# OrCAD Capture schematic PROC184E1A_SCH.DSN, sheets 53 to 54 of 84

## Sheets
53 58. USB TYPE C 3.1: size C; title: USB 3.1 TYPE C INTERFACE; note: PROC184_SCH
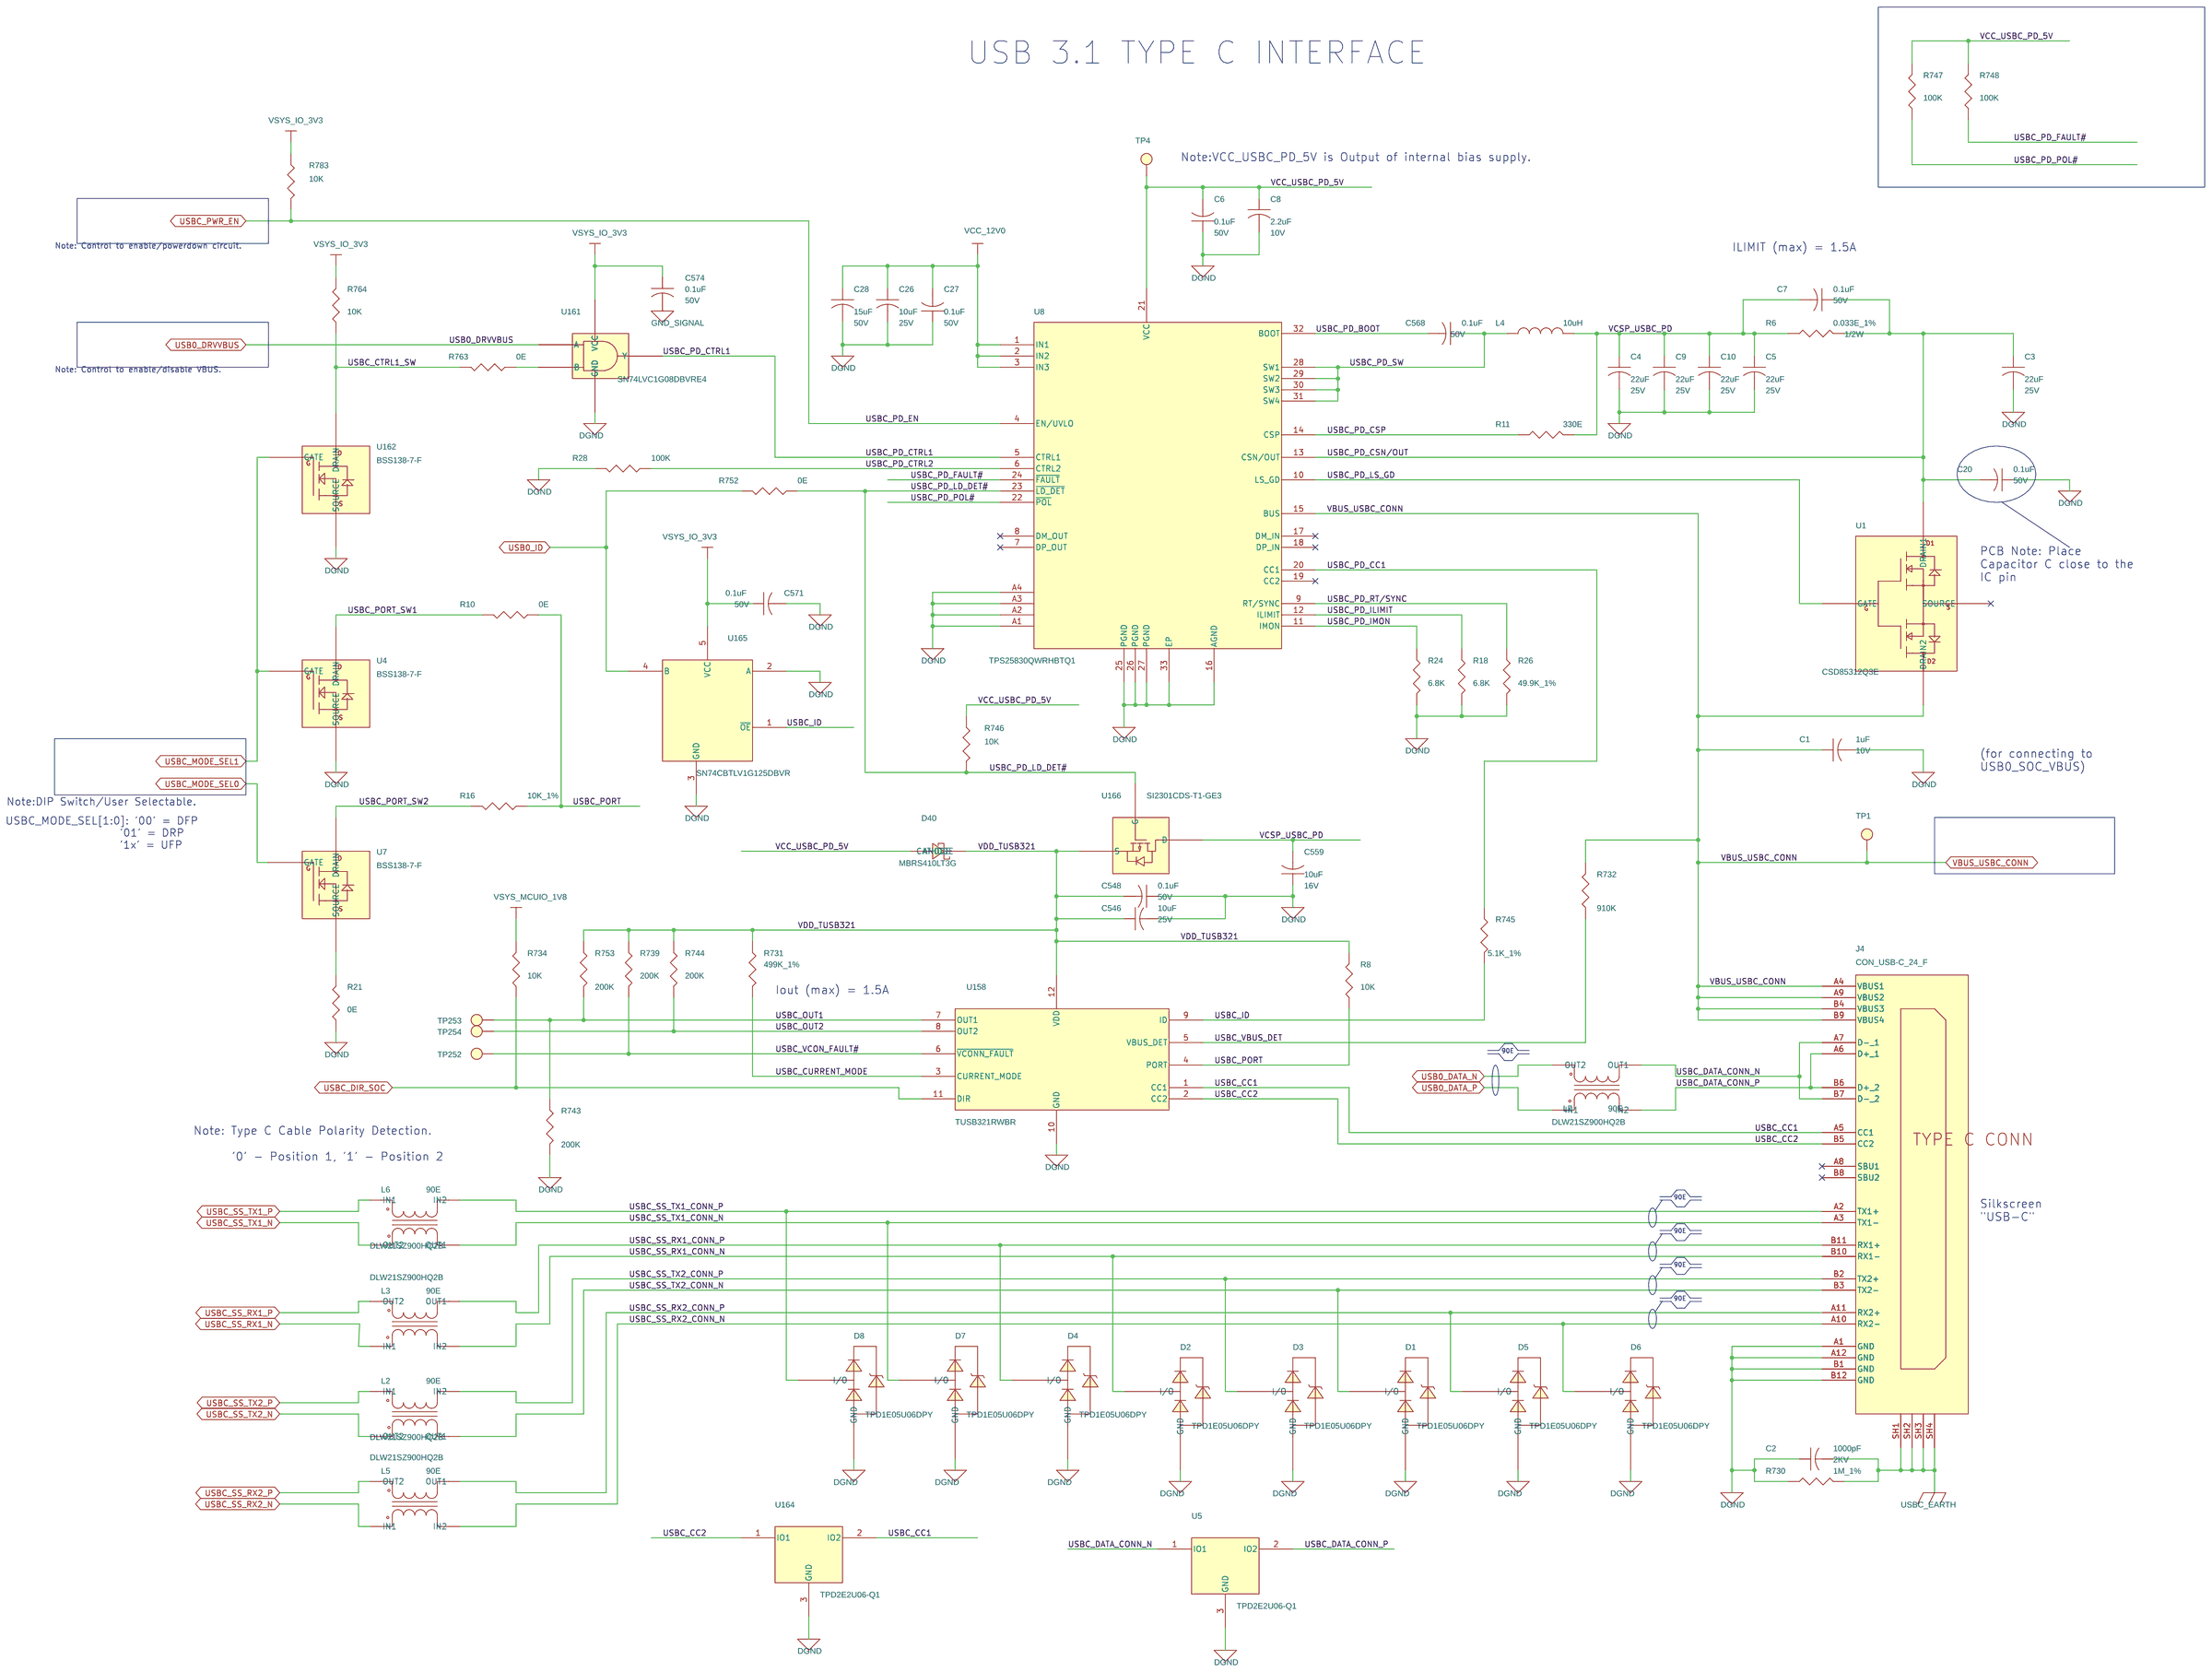
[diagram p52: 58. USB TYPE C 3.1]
54 32. SVS MONITOR: size C; title: SVS MONITOR; note: PROC184_SCH
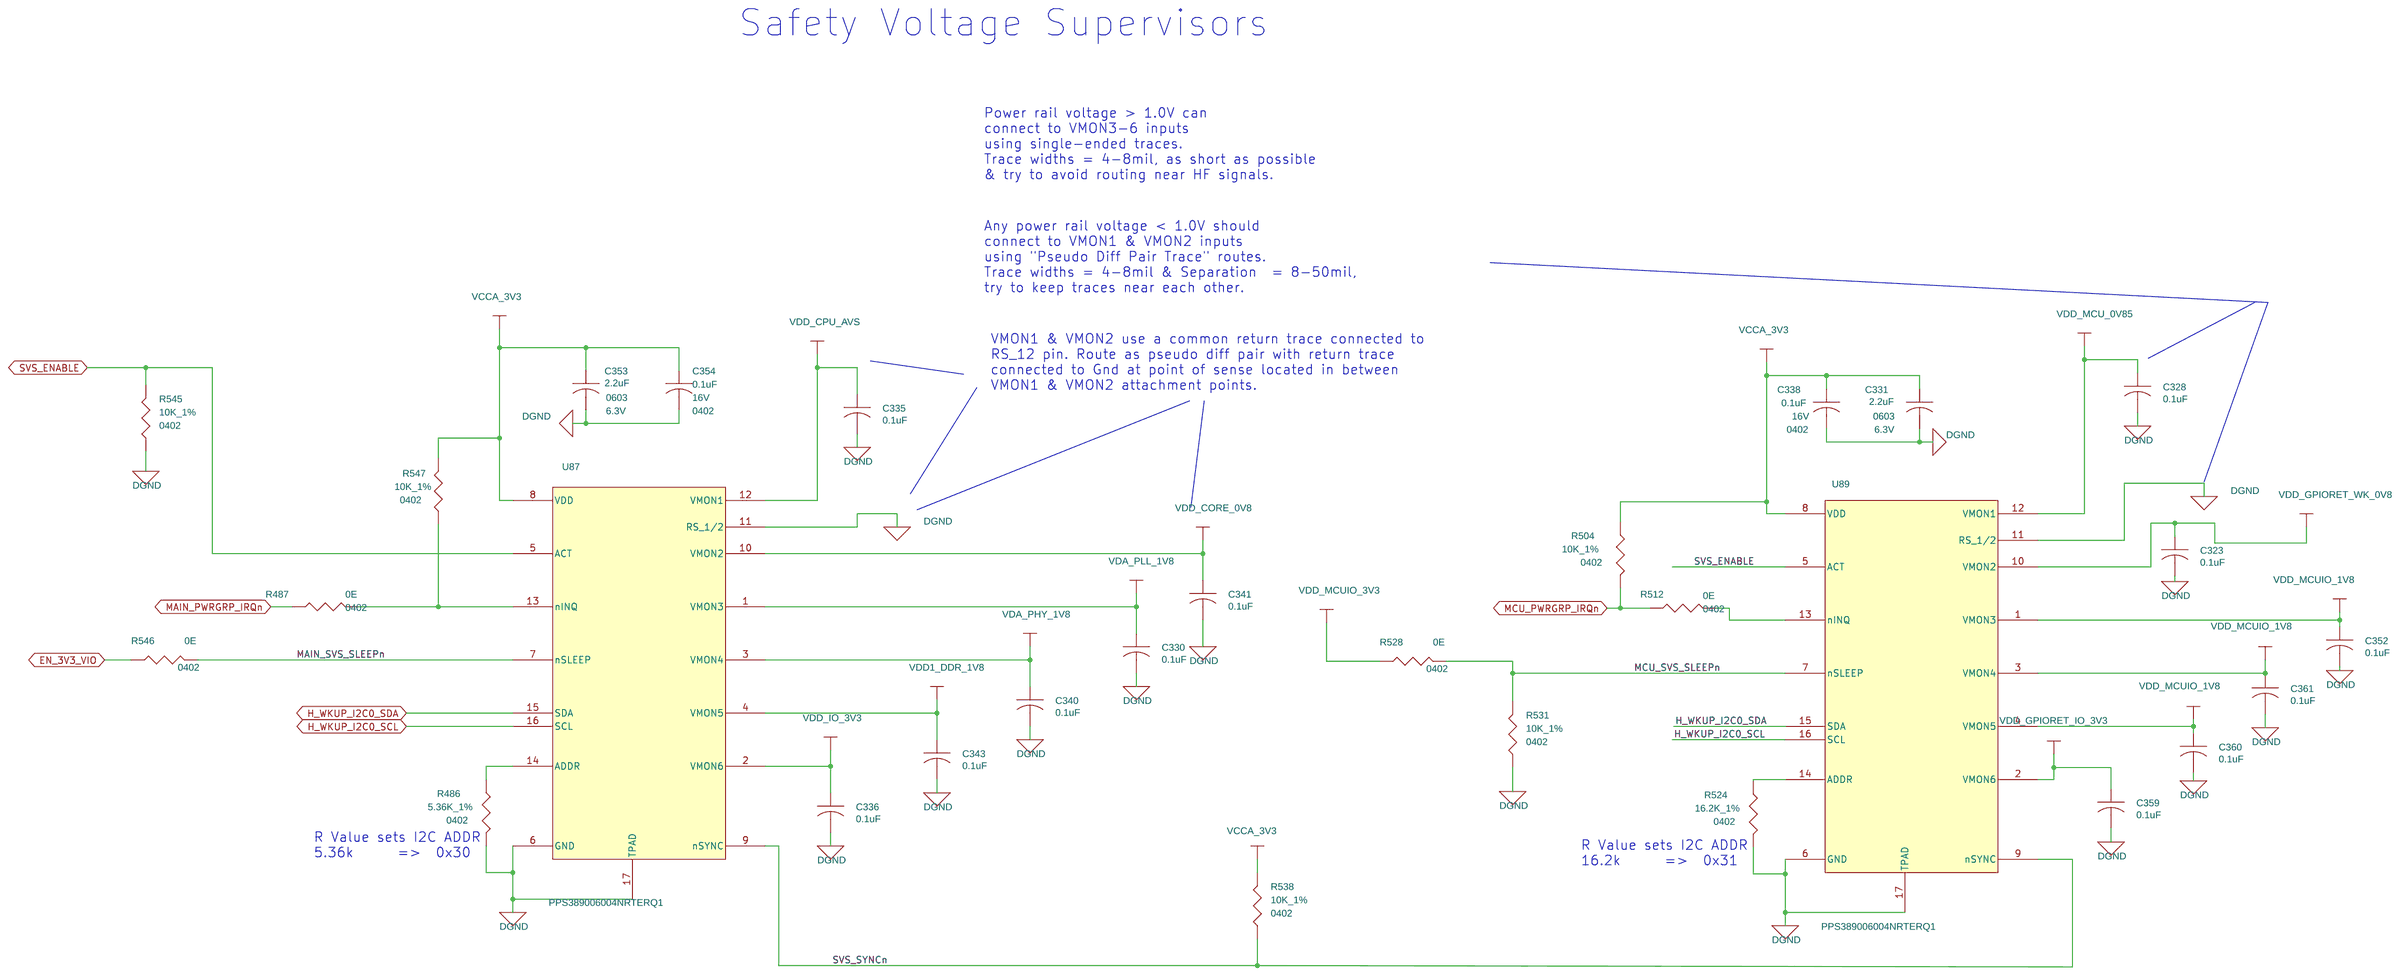
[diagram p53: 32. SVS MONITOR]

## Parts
sheet 32. SVS MONITOR
C323  0.1uF  [CAP0201_0-5]
C328  0.1uF  [CAP0201_0-5]
C330  0.1uF  [CAP0201_0-5]
C331  2.2uF  [CAP0603_1]
C335  0.1uF  [CAP0201_0-5]
C336  0.1uF  [CAP0201_0-5]
C338  0.1uF  [CAP0402_0-75]
C340  0.1uF  [CAP0201_0-5]
C341  0.1uF  [CAP0201_0-5]
C343  0.1uF  [CAP0201_0-5]
C352  0.1uF  [CAP0201_0-5]
C353  2.2uF  [CAP0603_1]
C354  0.1uF  [CAP0402_0-75]
C359  0.1uF  [CAP0201_0-5]
C360  0.1uF  [CAP0201_0-5]
C361  0.1uF  [CAP0201_0-5]
R486  5.36K_1%  [RES0402_0-5]
R487  0E  [RES0402_0-5]
R504  10K_1%  [RES0402_0-5]
R512  0E  [RES0402_0-5]
R524  16.2K_1%  [RES0402_0-5]
R528  0E  [RES0402_0-5]
R531  10K_1%  [RES0402_0-5]
R538  10K_1%  [RES0402_0-5]
R545  10K_1%  [RES0402_0-5]
R546  0E  [RES0402_0-5]
R547  10K_1%  [RES0402_0-5]
U87  PPS389006004NRTERQ1  [QFN16_19-68_120X120_0-8_EP1-8]
U89  PPS389006004NRTERQ1  [QFN16_19-68_120X120_0-8_EP1-8]
sheet 58. USB TYPE C 3.1
C1  1uF  [CAP0402_0-75]
C2  1000pF  [CAP1206_1-75]
C3  22uF  [CAP0805_1-5]
C4  22uF  [CAP0805_1-5]
C5  22uF  [CAP0805_1-5]
C6  0.1uF  [CAP0402_0-75]
C7  0.1uF  [CAP0402_0-75]
C8  2.2uF  [CAP0402_0-75]
C9  22uF  [CAP0805_1-5]
C10  22uF  [CAP0805_1-5]
C20  0.1uF  [CAP0402_0-75]
C26  10uF  [CAP0603_1-25]
C27  0.1uF  [CAP0402_0-75]
C28  15uF  [CAP2220_2-75]
C546  10uF  [CAP0603_1-25]
C548  0.1uF  [CAP0402_0-75]
C559  10uF  [CAP0805_1-5]
C568  0.1uF  [CAP0402_0-75]
C571  0.1uF  [CAP0402_0-75]
C574  0.1uF  [CAP0402_0-75]
D1  TPD1E05U06DPY  [DIO_DFN0402_0-5]
D2  TPD1E05U06DPY  [DIO_DFN0402_0-5]
D3  TPD1E05U06DPY  [DIO_DFN0402_0-5]
D4  TPD1E05U06DPY  [DIO_DFN0402_0-5]
D5  TPD1E05U06DPY  [DIO_DFN0402_0-5]
D6  TPD1E05U06DPY  [DIO_DFN0402_0-5]
D7  TPD1E05U06DPY  [DIO_DFN0402_0-5]
D8  TPD1E05U06DPY  [DIO_DFN0402_0-5]
D40  MBRS410LT3G  [DIO_SMC]
J4  CON_USB-C_24_F  [CON_USBC24_2012670_S_R_S_3-9]
L2  90E  [IND4_DLW21H_90X60_SMD_1-4]
L3  90E  [IND4_DLW21H_90X60_SMD_1-4]
L4  10uH  [IND_ASPI-0603LR_270X270_SMD_3]
L5  90E  [IND4_DLW21H_90X60_SMD_1-4]
L6  90E  [IND4_DLW21H_90X60_SMD_1-4]
L7  90E  [IND4_DLW21H_90X60_SMD_1-4]
R6  0.033E_1%  [RES1210_0-75]
R8  10K  [RES0402_0-5]
R10  0E  [RES0402_0-5]
R11  330E  [RES0402_0-5]
R16  10K_1%  [RES0402_0-5]
R18  6.8K  [RES0402_0-5]
R21  0E  [RES0402_0-5]
R24  6.8K  [RES0402_0-5]
R26  49.9K_1%  [RES0402_0-5]
R28  100K  [RES0402_0-5]
R730  1M_1%  [RES0805_0-75]
R731  499K_1%  [RES0402_0-5]
R732  910K  [RES0402_0-5]
R734  10K  [RES0402_0-5]
R739  200K  [RES0402_0-5]
R743  200K  [RES0402_0-5]
R744  200K  [RES0402_0-5]
R745  5.1K_1%  [RES0402_0-5]
R746  10K  [RES0402_0-5]
R747  100K  [RES0402_0-5]
R748  100K  [RES0402_0-5]
R752  0E  [RES0402_0-5]
R753  200K  [RES0402_0-5]
R763  0E  [RES0402_0-5]
R764  10K  [RES0402_0-5]
R783  10K  [RES0402_0-5]
TP1  THRU HOLE  [TP_40X65]
TP4  TP30_SMD  [TP30_SMD]
TP252  TP30_SMD  [TP30_SMD]
TP253  TP30_SMD  [TP30_SMD]
TP254  TP30_SMD  [TP30_SMD]
U1  CSD85312Q3E  [VSON8_CSD85312Q3E_130X130_1]
U4  BSS138-7-F  [SOT23-123_1-1]
U5  TPD2E2U06-Q1  [SC70-3_1-1]
U7  BSS138-7-F  [SOT23-123_1-1]
U8  TPS25830QWRHBTQ1  [VQFN32_TPS25830-Q1_200X200_1]
U158  TUSB321RWBR  [X2QFN12_TUSB322I_60X60_0-4]
U161  SN74LVC1G08DBVRE4  [SOT23-5]
U162  BSS138-7-F  [SOT23-123_1-1]
U164  TPD2E2U06-Q1  [SC70-3_1-1]
U165  SN74CBTLV1G125DBVR  [SOT23-5]
U166  SI2301CDS-T1-GE3  [SOT23-123]

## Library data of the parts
C323 C328 C330 C335 C336 C340 C341 C343 C352 C359-C361 = CAP: CAP CERAMIC 0.1uF 6.3V 10% X7S AUTO 0201; Chkd/date: MANIRAJA/011018; Crtd /date: MANIRAJA/011018; Custom_Duty: 15%; Customs_HS_Code: 85322990; Distributor_name: NA; Distributor_part_number: NA; Footprint Path: Y:\MIS_DATABASE\Library\ALTIUM_TOOL\PCB_FOOTPRINTS\Altium_Footprint_Lib.PcbLib; Height: 0.33MM; Library Path: Y:\MIS_DATABASE\Library\ALTIUM_TOOL\SCHEMATICS_PARTS\MS_DISCRETE_Library.schlib; Mfr_name: MURATA; Mfr_part_number: GCM033C70J104KE02D; Mistral Part No: 120018100001-R; Package: 0201; Part_type: CAPACITORS\CERAMIC; Project: TI_J7_SVB-DUT; RoHS: RoHS; Temperature: -55°C+125°C; Tolerance: 10%; Voltage: 6.3V; Wattage: NA; Weight: NA; Datasheet: Y:\MIS_DATABASE\DATASHEETS\CAPACITORS\MURATA-GCM-SER.PDF
C331 C353 = CAP: CAP CERAMIC 2.2uF 6.3V 10% X7R AUTO 0603; Automotive Alternate_mfr_name: TDK; Automotive Alternate_mfr_part_number: CGA3E1X7R0J225K080AC; Chkd/date: MANIRAJA/050419; Crtd /date: ALVY/050419; Custom_Duty: 15%; Customs_HS_Code: 85322990; Direct Alternate_mfr_name: TDK; Direct Alternate_mfr_part_number: CGA3E1X7R0J225K080AC; Distributor_name: DIGIKEY; Distributor_part_number: 490-5316-1-ND; Footprint Path: Y:\MIS_DATABASE\Library\ALTIUM_TOOL\PCB_FOOTPRINTS\Altium_Footprint_Lib.PcbLib; Height: 0.90MM; Library Path: Y:\MIS_DATABASE\Library\ALTIUM_TOOL\SCHEMATICS_PARTS\MS_DISCRETE_Library.schlib; Manufacturer: MURATA; Mfr_name: MURATA; Mfr_part_number: GCM188R70J225KE22D; Mistral Part No: 120019040009-R; Package: 0603; Part_type: CAPACITORS\CERAMIC; Project: J7ES_SOM_DUAL-LEO_PMIC; RoHS: RoHS; Temperature: -55°C+125°C; Tolerance: 10%; Voltage: 6.3V; Wattage: NA; Weight: 6.3mg; Datasheet: Y:\MIS_DATABASE\DATASHEETS\CAPACITORS\GCM188R70J225KE22.PDF
C338 C354 = CAP: CAP CERAMIC 0.1uF 16V 10% X7R AUTO 0402; Automotive Alternate_mfr_name: TDK; Automotive Alternate_mfr_part_number: CGA2B1X7R1C104K050BC; Chkd/date: NAVEED/021014; Crtd /date: VASANTHA/300514; Custom_Duty: 15%; Customs_HS_Code: 85322990; Direct Alternate_mfr_name: MURATA; Direct Alternate_mfr_part_number: GCM155R71C104JA55D; Distributor_name: DIGIKEY; Distributor_part_number: 490-4759-1-ND; Footprint Path: Y:\MIS_DATABASE\Library\ALTIUM_TOOL\PCB_FOOTPRINTS\Altium_Footprint_Lib.PcbLib; Height: 0.55MM; Library Path: Y:\MIS_DATABASE\Library\ALTIUM_TOOL\SCHEMATICS_PARTS\MS_DISCRETE_Library.schlib; Manufacturer: MURATA; Mfr_name: MURATA; Mfr_part_number: GCM155R71C104KA55D; Mistral Part No: 120016070006-R; Package: 0402; Part_type: CAPACITORS\CERAMIC; Project: DCMIST_FPGA_CARD; RoHS: RoHS; Temperature: -55°C+125°C; Tolerance: 10%; Voltage: 16V; Wattage: NA; Weight: 6mg; Datasheet: Y:\MIS_DATABASE\DATASHEETS\CAPACITORS\MURATA-GCM-SER.PDF
R486 = RESISTOR: RES 5.36K 1/16W 1% 0402; Chkd/date: MANIRAJA/120617; Crtd /date: BAVISH/220611; Custom_Duty: 15%; Customs_HS_Code: 85332119; Distributor_name: DIGIKEY; Distributor_part_number: 541-5.36KLCT-ND; Footprint Path: Y:\MIS_DATABASE\Library\ALTIUM_TOOL\PCB_FOOTPRINTS\Altium_Footprint_Lib.PcbLib; Height: 0.40MM; Library Path: Y:\MIS_DATABASE\Library\ALTIUM_TOOL\SCHEMATICS_PARTS\MS_DISCRETE_Library.schlib; Manufacturer: YAGEO AMERICA; Mfr_name: VISHAY; Mfr_part_number: CRCW04025K36FKED; Mistral Part No: 110011060044-R; Package: 0402; Part_type: RESISTORS\FIXED; Project: ITS-PWR_CARD; RoHS: RoHS; Temperature: -55°C+155°C; Tolerance: 1%; Voltage: NA; Wattage: 1/16W; Weight: 0.65mg; Datasheet: Y:\MIS_DATABASE\DATASHEETS\RESISTORS\CRCW0603.PDF
R10 R21 R487 R512 R528 R546 R763 = RESISTOR: RES 0E 1/10W JUMPER 0402; Chkd/date: VASANTHA/061216; Crtd /date: NAVEED/201014; Custom_Duty: 15%; Customs_HS_Code: 85332119; Distributor_name: DIGIKEY; Distributor_part_number: P0.0JCT-ND; Footprint Path: Y:\MIS_DATABASE\Library\ALTIUM_TOOL\PCB_FOOTPRINTS\Altium_Footprint_Lib.PcbLib; Height: 0.40MM; IBISSP_MODLES: VALUE REPEATING 2 TIME; Library Path: Y:\MIS_DATABASE\Library\ALTIUM_TOOL\SCHEMATICS_PARTS\MS_DISCRETE_Library.schlib; Manufacturer: PANASONIC-ECG; Mfr_name: PANASONIC-ECG; Mfr_part_number: ERJ-2GE0R00X; Mistral Part No: 110018030052-R; Package: 0402; Part_type: RESISTORS\FIXED; Project: AEGIS POM; RoHS: RoHS; Temperature: -55°C+155°C; Tolerance: NA; Voltage: NA; Wattage: 1/10W; Weight: 0.8mg; Datasheet: Y:\MIS_DATABASE\DATASHEETS\RESISTORS\PAN-ERJSER_NOV17.PDF
R16 R504 R531 R538 R545 R547 = RESISTOR: RES 10K 1/16W 1% 0402; Chkd/date: VASANTHA/201216; Crtd /date: GEETHA/290506; Custom_Duty: 15%; Customs_HS_Code: 85332119; Distributor_name: DIGIKEY; Distributor_part_number: 311-10.0KLRTR-ND; Footprint Path: Y:\MIS_DATABASE\Library\ALTIUM_TOOL\PCB_FOOTPRINTS\Altium_Footprint_Lib.PcbLib; Height: 0.40MM; Library Path: Y:\MIS_DATABASE\Library\ALTIUM_TOOL\SCHEMATICS_PARTS\MS_DISCRETE_Library.schlib; Manufacturer: YAGEO AMERICA; Mfr_name: YAGEO AMERICA; Mfr_part_number: RC0402FR-0710KL; Mistral Part No: 110015090015-R; Package: 0402; Part_type: RESISTORS\FIXED; Project: VOCERA; RoHS: RoHS; Temperature: -55°C+155°C; Tolerance: 1%; Voltage: NA; Wattage: 1/16W; Weight: 0.65mg; Datasheet: Y:\MIS_DATABASE\DATASHEETS\RESISTORS\RCXXXXL-SER_MAR18.PDF
R524 = RESISTOR: RES 16.2K 1/16W 1% AUTO 0402; Chkd/date: MANIRAJA/130617; Crtd /date: MAZHAR/270809; Custom_Duty: 15%; Customs_HS_Code: 85332119; Distributor_name: DIGIKEY; Distributor_part_number: RHM16.2KLCT-ND; Footprint Path: Y:\MIS_DATABASE\Library\ALTIUM_TOOL\PCB_FOOTPRINTS\Altium_Footprint_Lib.PcbLib; Height: 0.40MM; Library Path: Y:\MIS_DATABASE\Library\ALTIUM_TOOL\SCHEMATICS_PARTS\MS_DISCRETE_Library.schlib; Manufacturer: YAGEO AMERICA; Mfr_name: ROHM; Mfr_part_number: MCR01MZPF1622; Mistral Part No: 110009080027-R; Package: 0402; Part_type: RESISTORS\FIXED; Project: GEACOM_PHRAZER; RoHS: RoHS; Temperature: -55°C+155°C; Tolerance: 1%; Voltage: NA; Wattage: 1/16W; Weight: 0.57mg; Datasheet: Y:\MIS_DATABASE\DATASHEETS\RESISTORS\MCR10.PDF
U87 U89 = PPS38900603NRTERQ1_WQFN16: IC MULTI-CH OVERVOLTAGE AND UNDERVOLTAGE I2C PROGRAMMABLE VOLTAGE SUPERVISOR AND MONITOR WQFN16; Chkd/date: PRAVEEN/190722; Crtd /date: TAMILARASU/210722; Custom_Duty: 15%; Customs_HS_Code: 85423100; Distributor_name: NA; Distributor_part_number: NA; Footprint Path: Y:\MIS_DATABASE\Library\ALTIUM_TOOL\PCB_FOOTPRINTS\Altium_Footprint_Lib.PcbLib; Height: 0.80MM; Library Path: Y:\MIS_DATABASE\Library\ALTIUM_TOOL\SCHEMATICS_PARTS\MS_MISCPOWER_Library.schlib; Mfr_name: TEXAS INSTRUMENTS; Mistral Part No: 142022070022-R; Package: WQFN16; Part_type: ICS\POWER\MANAGEMENT; Project: TI_J7AHP_EVM_BRD; RoHS: NA; Temperature: -40°C+125°C; Tolerance: NA; Voltage: NA; Wattage: NA; Weight: NA; Datasheet: Y:\MIS_DATABASE\DATASHEETS\ICS\POWER\TPS389006-Q1.PDF
C1 = CAP: CAP CERAMIC 1uF 10V 10% X7S AUTO 0402; Automotive Alternate_mfr_name: TAIYO YUDEN; Automotive Alternate_mfr_part_number: EMK105BJ105KVHF; Chkd/date: MANIRAJA/100918; Crtd /date: ALVY/100918; Custom_Duty: 15%; Customs_HS_Code: 85322990; Direct Alternate_mfr_name: YAGEO AMERICA; Direct Alternate_mfr_part_number: CC0402KRX5R7BB105; Distributor_name: DIGIKEY; Distributor_part_number: 490-13409-1-ND; Footprint Path: Y:\MIS_DATABASE\Library\ALTIUM_TOOL\PCB_FOOTPRINTS\Altium_Footprint_Lib.PcbLib; Height: 0.70MM; Library Path: Y:\MIS_DATABASE\Library\ALTIUM_TOOL\SCHEMATICS_PARTS\MS_DISCRETE_Library.schlib; Manufacturer: TDK CORPORATION; Mfr_name: MURATA; Mfr_part_number: GCM155C71A105KE38D; Mistral Part No: 120018090021-R; Package: 0402; Part_type: CAPACITORS\CERAMIC; Project: SMART-M_SCRIPTALK_PB; RoHS: RoHS; Temperature: -55°C+125°C; Tolerance: 10%; Voltage: 10V; Wattage: NA; Weight: 6mg; Datasheet: Y:\MIS_DATABASE\DATASHEETS\CAPACITORS\MURATA-GCM-SER.PDF
C2 = CAP: CAP CERAMIC 1000pF 2KV 10% X7R 1206; Automotive Alternate_mfr_name: KEMET; Automotive Alternate_mfr_part_number: C1206X102KGRACAUTO; Chkd/date: SHREESHAIL/291106; Crtd /date: MAZHAR/281106; Custom_Duty: 15%; Customs_HS_Code: 85322990; Direct Alternate_mfr_name: KEMET; Direct Alternate_mfr_part_number: C1206C102KGRACTU; Distributor_name: DIGIKEY; Distributor_part_number: 478-2956-1-ND; Footprint Path: Y:\MIS_DATABASE\Library\ALTIUM_TOOL\PCB_FOOTPRINTS\Altium_Footprint_Lib.PcbLib; Height: 1.52MM; Library Path: Y:\MIS_DATABASE\Library\ALTIUM_TOOL\SCHEMATICS_PARTS\MS_DISCRETE_Library.schlib; Manufacturer: AVX CORPORATION; Mfr_name: AVX CORPORATION; Mfr_part_number: 1206GC102KAT1A; Mistral Part No: 120015080006-R; Package: 1206; Part_type: CAPACITORS\CERAMIC; Project: ADR1B; RoHS: RoHS; Temperature: -55°C+125°C; Tolerance: 10%; Voltage: 2KV; Wattage: NA; Weight: 16.2mg; Datasheet: Y:\MIS_DATABASE\DATASHEETS\CAPACITORS\AVX_HV-MLC.PDF
C3-C5 C9 C10 = CAP: CAP CERAMIC 22uF 25V 20% X5R 0805; Automotive Alternate_mfr_name: MURATA; Automotive Alternate_mfr_part_number: GRT21BR61E226ME13L; Chkd/date: USMAN/191213; Crtd /date: USMAN/191213; Custom_Duty: 15%; Customs_HS_Code: 85322990; Direct Alternate_mfr_name: MURATA; Direct Alternate_mfr_part_number: GRM21BR61E226ME44L; Distributor_name: DIGIKEY; Distributor_part_number: 1276-2908-1-ND; Footprint Path: Y:\MIS_DATABASE\Library\ALTIUM_TOOL\PCB_FOOTPRINTS\Altium_Footprint_Lib.PcbLib; Height: 1.40MM; Library Path: Y:\MIS_DATABASE\Library\ALTIUM_TOOL\SCHEMATICS_PARTS\MS_DISCRETE_Library.schlib; Manufacturer: SAMSUNG; Mfr_name: SAMSUNG; Mfr_part_number: CL21A226MAQNNNE; Mistral Part No: 120013120018-R; Package: 0805; Part_type: CAPACITORS\CERAMIC; Project: ITS2_RF; RoHS: RoHS; Temperature: -55°C+85°C; Tolerance: 20%; Voltage: 25V; Wattage: NA; Weight: 5.5mg; Datasheet: Y:\MIS_DATABASE\DATASHEETS\CAPACITORS\CL_SERIES.PDF
C6 C7 C20 C548 C568 C571 C574 = CAP: CAP CERAMIC 0.1uF 50V 10% X7R 0402; Automotive Alternate_mfr_name: TDK; Automotive Alternate_mfr_part_number: CGA2B3X7R1H104K050BB; Chkd/date: MANIRAJA/261020; Crtd /date: ALVY/211020; Custom_Duty: 15%; Customs_HS_Code: 85322990; Direct Alternate_mfr_name: TDK; Direct Alternate_mfr_part_number: C1005X7R1H104K050BE; Distributor_name: DIGIKEY; Distributor_part_number: 490-10700-1-ND; Footprint Path: Y:\MIS_DATABASE\Library\ALTIUM_TOOL\PCB_FOOTPRINTS\Altium_Footprint_Lib.PcbLib; Height: 0.55MM; Library Path: Y:\MIS_DATABASE\Library\ALTIUM_TOOL\SCHEMATICS_PARTS\MS_DISCRETE_Library.schlib; Manufacturer: MURATA; Mfr_name: MURATA; Mfr_part_number: GRM155R71H104KE14D; Mistral Part No: 120011100014-R; Package: 0402; Part_type: CAPACITORS\CERAMIC; Project: J7_CP; RoHS: RoHS; Temperature: -55°C+125°C; Tolerance: 10%; Voltage: 50V; Wattage: NA; Weight: 3.1mg; Datasheet: Y:\MIS_DATABASE\DATASHEETS\CAPACITORS\GRM155R71H104KE14.PDF
C8 = CAP: CAP CERAMIC 2.2uF 10V 10% X5R 0402; Automotive Alternate_mfr_name: MURATA; Automotive Alternate_mfr_part_number: GRT155R61E225KE13D; Chkd/date: MANIRAJA/251120; Crtd /date: ALVY/241120; Custom_Duty: 15%; Customs_HS_Code: 85322990; Direct Alternate_mfr_name: TDK; Direct Alternate_mfr_part_number: C1005X5R1E225K050BC; Distributor_name: MOUSER; Distributor_part_number: 81-GRM155R61A225K01D; Footprint Path: Y:\MIS_DATABASE\Library\ALTIUM_TOOL\PCB_FOOTPRINTS\Altium_Footprint_Lib.PcbLib; Height: 0.55MM; Library Path: Y:\MIS_DATABASE\Library\ALTIUM_TOOL\SCHEMATICS_PARTS\MS_DISCRETE_Library.schlib; Manufacturer: MURATA; Mfr_name: MURATA; Mfr_part_number: GRM155R61A225KE01D; Mistral Part No: 120011100038-R; Package: 0402; Part_type: CAPACITORS\CERAMIC; Project: PLCC_DIGITAL BRD PROTO; RoHS: RoHS; Temperature: -55°C+85°C; Tolerance: 10%; Voltage: 10V; Wattage: NA; Weight: 1.6mg; Datasheet: Y:\MIS_DATABASE\DATASHEETS\CAPACITORS\MURATA-GXX-SER_NOV17.PDF
C26 C546 = CAP: CAP CERAMIC 10uF 25V 20% X5R 0603; Automotive Alternate_mfr_name: TDK; Automotive Alternate_mfr_part_number: CGA5L1X7R1H106K160AC; Chkd/date: MANIRAJA/040718; Crtd /date: MANIRAJA/040718; Custom_Duty: 15%; Customs_HS_Code: 85322990; Direct Alternate_mfr_name: SAMSUNG; Direct Alternate_mfr_part_number: CL31A106KBHNNNE; Distributor_name: DIGIKEY; Distributor_part_number: 490-10991-1-ND; Footprint Path: Y:\MIS_DATABASE\Library\ALTIUM_TOOL\PCB_FOOTPRINTS\Altium_Footprint_Lib.PcbLib; Height: 1.20MM; Library Path: Y:\MIS_DATABASE\Library\ALTIUM_TOOL\SCHEMATICS_PARTS\MS_DISCRETE_Library.schlib; Manufacturer: TDK CORPORATION; Mfr_name: MURATA; Mfr_part_number: ZRB18AR61E106ME01L; Mistral Part No: 120018070001-R; Package: 0603; Part_type: CAPACITORS\CERAMIC; Project: CABS_VME_DIO; RoHS: RoHS; Temperature: -55°C+85°C; Tolerance: 20%; Voltage: 25V; Wattage: NA; Weight: 2mg; Datasheet: Y:\MIS_DATABASE\DATASHEETS\CAPACITORS\ZRB18AR61E106ME01L.PDF
C27 = CAP: CAP CERAMIC 0.1uF 50V 10% X7R 0402; Automotive Alternate_mfr_name: TDK; Automotive Alternate_mfr_part_number: CGA5L2X7R2A104K160AA; Chkd/date: MANIRAJA/261020; Crtd /date: ALVY/211020; Custom_Duty: 15%; Customs_HS_Code: 85322990; Direct Alternate_mfr_name: TDK; Direct Alternate_mfr_part_number: C3216X7R2A104K160AA; Distributor_name: DIGIKEY; Distributor_part_number: 490-10700-1-ND; Footprint Path: Y:\MIS_DATABASE\Library\ALTIUM_TOOL\PCB_FOOTPRINTS\Altium_Footprint_Lib.PcbLib; Height: 0.55MM; Library Path: Y:\MIS_DATABASE\Library\ALTIUM_TOOL\SCHEMATICS_PARTS\MS_DISCRETE_Library.schlib; Manufacturer: AVX CORPORATION; Mfr_name: MURATA; Mfr_part_number: GRM155R71H104KE14D; Mistral Part No: 120011100014-R; Package: 0402; Part_type: CAPACITORS\CERAMIC; Project: J7_CP; RoHS: RoHS; Temperature: -55°C+125°C; Tolerance: 10%; Voltage: 50V; Wattage: NA; Weight: 3.1mg; Datasheet: Y:\MIS_DATABASE\DATASHEETS\CAPACITORS\GRM155R71H104KE14.PDF
C28 = CAP: CAP CERAMIC 15uF 50V 10% X7R 2220; Automotive Alternate_mfr_name: KEMET; Automotive Alternate_mfr_part_number: C2220X156K5RACAUTO; Chkd/date: MANIRAJA/121018; Crtd /date: MANIRAJA/121018; Custom_Duty: 15%; Customs_HS_Code: 85322990; Direct Alternate_mfr_name: UNITED CHEMI-CON; Direct Alternate_mfr_part_number: KTS500B156M55N0T00; Distributor_name: DIGIKEY; Distributor_part_number: 399-10019-2-ND; Footprint Path: Y:\MIS_DATABASE\Library\ALTIUM_TOOL\PCB_FOOTPRINTS\Altium_Footprint_Lib.PcbLib; Height: 2.55MM; Library Path: Y:\MIS_DATABASE\Library\ALTIUM_TOOL\SCHEMATICS_PARTS\MS_DISCRETE_Library.schlib; Manufacturer: KEMET; Mfr_name: KEMET; Mfr_part_number: C2220C156K5RACTU; Mistral Part No: 120018100024-R; Package: 2220; Part_type: CAPACITORS\CERAMIC; Project: TI_J7ES_EVM_CP; RoHS: RoHS; Temperature: -55°C+125°C; Tolerance: 10%; Voltage: 50V; Wattage: NA; Weight: 480mg; Datasheet: Y:\MIS_DATABASE\DATASHEETS\CAPACITORS\KEMET-C-X7R.PDF
C559 = CAP: CAP CERAMIC 10uF 16V 10% X5R 0805; Automotive Alternate_mfr_name: TDK; Automotive Alternate_mfr_part_number: CGA4J1X7S1C106K125AC; Chkd/date: SHREESHAIL/220506; Crtd /date: MAZHAR/150506; Custom_Duty: 15%; Customs_HS_Code: 85322990; Direct Alternate_mfr_name: TDK; Direct Alternate_mfr_part_number: C2012X7S1C106K125AC; Distributor_name: DIGIKEY; Distributor_part_number: 490-3886-1-ND; Footprint Path: Y:\MIS_DATABASE\Library\ALTIUM_TOOL\PCB_FOOTPRINTS\Altium_Footprint_Lib.PcbLib; Height: 1.35MM; Library Path: Y:\MIS_DATABASE\Library\ALTIUM_TOOL\SCHEMATICS_PARTS\MS_DISCRETE_Library.schlib; Manufacturer: MURATA; Mfr_name: MURATA; Mfr_part_number: GRM21BR61C106KE15L; Mistral Part No: 120009030205-R; Package: 0805; Part_type: CAPACITORS\CERAMIC; Project: VOCERA; RoHS: RoHS; Temperature: -55°C+85°C; Tolerance: 10%; Voltage: 16V; Wattage: NA; Weight: 9.5mg; Datasheet: Y:\MIS_DATABASE\DATASHEETS\CAPACITORS\MURATA-GXX-SER_NOV17.PDF
D1-D8 = DIODE_TPD1E05U06: DIODE 1CH ESD PROTECTION FOR INTERFACE X1SON2; Chkd/date: MANIRAJA/290618; Crtd /date: MANIRAJA/290618; Custom_Duty: 15%; Customs_HS_Code: 85412900; Distributor_name: DIGIKEY; Distributor_part_number: 296-39342-1-ND; Footprint Path: Y:\MIS_DATABASE\Library\ALTIUM_TOOL\PCB_FOOTPRINTS\Altium_Footprint_Lib.PcbLib; Height: 0.45MM; Library Path: Y:\MIS_DATABASE\Library\ALTIUM_TOOL\SCHEMATICS_PARTS\MS_DISCRETE_Library.schlib; Manufacturer: TEXAS INSTRUMENTS; Mfr_name: TEXAS INSTRUMENTS; Mfr_part_number: TPD1E05U06DPYT; Mistral Part No: 130018060037-R; Package: X1SON2; Part_type: DIODE\TVS; Project: GOLDEN-I LITE; RoHS: RoHS; Temperature: -40°C+125°C; Tolerance: NA; Voltage: NA; Wattage: NA; Weight: 1mg; Datasheet: Y:\MIS_DATABASE\DATASHEETS\DISCRETES\DIODES\TPDXE05U06.PDF
D40 = DIODE_SCHOTTKY: DIODE SCHOTTKY 40V 5A SMC; Chkd/date: RAGESH/130411; Crtd /date: BAVISH/110311; Custom_Duty: 15%; Customs_HS_Code: 85412900; Distributor_name: DIGIKEY; Distributor_part_number: MBRS410LT3GOSCT-ND; Height: 2.41MM; Manufacturer: ON SEMICONDUCTOR; Mfr_name: ON SEMICONDUCTOR; Mistral Part No: 130011030001-R; Package: SMC; Part_type: DIODE\SCHOTTKY; Project: ALLYCAT; RoHS: RoHS; Temperature: -65°C+150°C; Tolerance: NA; Voltage: 10V; Wattage: NA; Weight: 217mg; Datasheet: Y:\MIS_DATABASE\DATASHEETS\DISCRETES\DIODES\MBRS410LT3G.PDF
J4 = CON_USB-C_24_1240183621_TI: CON USB-C TYPE 24POS FEMALE RT SMD; Chkd/date: MANIRAJA/050618; Crtd /date: ALVY/040618; Custom_Duty: 24%; Customs_HS_Code: 85369090; Distributor_name: DIGIKEY; Distributor_part_number: WM17992CT-ND; Footprint Path: Y:\MIS_DATABASE\Library\ALTIUM_TOOL\PCB_FOOTPRINTS\Altium_Footprint_Lib.PcbLib; Height: 3.86MM; Library Path: Y:\MIS_DATABASE\Library\ALTIUM_TOOL\SCHEMATICS_PARTS\MS_CONNECTOR_Library.schlib; Library Ref: CON_USB-C_24_1240183621; Manufacturer: MOLEX; Mfr_name: MOLEX; Mfr_part_number: 2012670005; Mistral Part No: 150018060002-R; Package: SMD; Part_type: CONNECTOR\USB; Project: TI_J7SVB_USB_ADD-ON-CARD; RoHS: RoHS; Temperature: -40°C+105°C; Tolerance: NA; Voltage: NA; Wattage: NA; Weight: 0.686g; Datasheet: Y:\MIS_DATABASE\DATASHEETS\CONNECTORS\2012670X.PDF
L2 L3 L5-L7 = INDUCTOR_DLW31S: IND COMMON MODE CHOKE 90E 280mA SMD; Chkd/date: MANIRAJA/270619; Crtd /date: MANIRAJA/270619; Custom_Duty: 24%; Customs_HS_Code: 85437099; Distributor_name: NA; Distributor_part_number: NA; Footprint Path: Y:\MIS_DATABASE\Library\ALTIUM_TOOL\PCB_FOOTPRINTS\Altium_Footprint_Lib.PcbLib; Height: 1.40MM; Library Path: Y:\MIS_DATABASE\Library\ALTIUM_TOOL\SCHEMATICS_PARTS\MS_DISCRETE_Library.schlib; Manufacturer: MURATA; Mfr_name: MURATA; Mfr_part_number: DLW21SZ900HQ2B; Mistral Part No: 130019060035-R; Package: SMD; Part_type: INDUCTOR; Project: TI_J7ES_CP; RoHS: RoHS; Temperature: -40°C+105°C; Tolerance: NA; Voltage: NA; Wattage: NA; Weight: 11mg; Datasheet: Y:\MIS_DATABASE\DATASHEETS\DISCRETES\INDUCTORS\DLW21SZ900HQ2B.PDF
L4 = INDUCTOR: IND POWER 10uH 4A 20% SMD; Automotive Alternate_mfr_name: TDK; Automotive Alternate_mfr_part_number: SPM6530T-100M-HZ; Chkd/date: VASANTHA/150217; Crtd /date: MANIRAJA/150217; Custom_Duty: 24%; Customs_HS_Code: 85437099; Direct Alternate_mfr_name: TDK; Direct Alternate_mfr_part_number: SPM6530T-100M; Distributor_name: DIGIKEY; Distributor_part_number: ASPI-0630LR-100M-T15CT-ND; Footprint Path: Y:\MIS_DATABASE\Library\ALTIUM_TOOL\PCB_FOOTPRINTS\Altium_Footprint_Lib.PcbLib; Height: 3.00MM; Library Path: Y:\MIS_DATABASE\Library\ALTIUM_TOOL\SCHEMATICS_PARTS\MS_DISCRETE_Library.schlib; Manufacturer: ABRACON; Mfr_name: ABRACON; Mfr_part_number: ASPI-0630LR-100M-T15; Mistral Part No: 130017020032-R; Package: SMD; Project: SD820_NANO_SOM; RoHS: RoHS; Temperature: -55°C+125°C; Tolerance: 20%; Voltage: NA; Wattage: NA; Weight: NA; Datasheet: Y:\MIS_DATABASE\DATASHEETS\DISCRETES\INDUCTORS\ASPI-0603LR.PDF
R6 = RESISTOR: RES 0.033E 1/2W 1% 1210; Chkd/date: JEBRAN/060215; Crtd /date: USMAN/010413; Custom_Duty: 15%; Customs_HS_Code: 85332119; Distributor_name: DIGIKEY; Distributor_part_number: 311-0.033NACT-ND; Footprint Path: Y:\MIS_DATABASE\Library\ALTIUM_TOOL\PCB_FOOTPRINTS\Altium_Footprint_Lib.PcbLib; Height: 0.65MM; Library Path: Y:\MIS_DATABASE\Library\ALTIUM_TOOL\SCHEMATICS_PARTS\MS_DISCRETE_Library.schlib; Manufacturer: YAGEO AMERICA; Mfr_name: YAGEO AMERICA; Mfr_part_number: RL1210FR-070R033L; Mistral Part No: 110013040001-R; Package: 1210; Part_type: RESISTORS\FIXED; Project: DTRM; RoHS: RoHS; Temperature: -55°C+155°C; Tolerance: 1%; Voltage: NA; Wattage: 1/2W; Weight: 16mg; Datasheet: Y:\MIS_DATABASE\DATASHEETS\RESISTORS\RLXXXXL-SER_JUN17.PDF
R8 R734 R746 R764 R783 = RESISTOR: RES 10K 1/16W 5% 0402; Chkd/date: VASANTHA/061216; Crtd /date: MAZHAR/230805; Custom_Duty: 15%; Customs_HS_Code: 85332119; Distributor_name: DIGIKEY; Distributor_part_number: 311-10KJRCT-ND; Footprint Path: Y:\MIS_DATABASE\Library\ALTIUM_TOOL\PCB_FOOTPRINTS\Altium_Footprint_Lib.PcbLib; Height: 0.40MM; Library Path: Y:\MIS_DATABASE\Library\ALTIUM_TOOL\SCHEMATICS_PARTS\MS_DISCRETE_Library.schlib; Manufacturer: YAGEO AMERICA; Mfr_name: YAGEO AMERICA; Mfr_part_number: RC0402JR-0710KL; Mistral Part No: 110011060021-R; Package: 0402; Part_type: RESISTORS\FIXED; Project: HSE; RoHS: RoHS; Temperature: -55°C+155°C; Tolerance: 5%; Voltage: NA; Wattage: 1/16W; Weight: 0.65mg; Datasheet: Y:\MIS_DATABASE\DATASHEETS\RESISTORS\RCXXXXL-SER_MAR18.PDF
R11 = RESISTOR: RES 330E 1/10W 5% 0402; Chkd/date: VASANTHA/281216; Crtd /date: USMAN/090309; Custom_Duty: 15%; Customs_HS_Code: 85332119; Distributor_name: DIGIKEY; Distributor_part_number: P330JCT-ND; Footprint Path: Y:\MIS_DATABASE\Library\ALTIUM_TOOL\PCB_FOOTPRINTS\Altium_Footprint_Lib.PcbLib; Height: 0.40MM; Library Path: Y:\MIS_DATABASE\Library\ALTIUM_TOOL\SCHEMATICS_PARTS\MS_DISCRETE_Library.schlib; Manufacturer: PANASONIC-ECG; Mfr_name: PANASONIC-ECG; Mfr_part_number: ERJ-2GEJ331X; Mistral Part No: 110009031217-R; Package: 0402; Part_type: RESISTORS\FIXED; Project: PC104-SBC; RoHS: RoHS; Temperature: -55°C+155°C; Tolerance: 5%; Voltage: NA; Wattage: 1/10W; Weight: 0.8mg; Datasheet: Y:\MIS_DATABASE\DATASHEETS\RESISTORS\PAN-ERJSER_NOV17.PDF
R18 R24 = RESISTOR: RES 6.8K 1/10W 5% 0402; Chkd/date: SUHAS/270910; Crtd /date: MAZHAR/061009; Custom_Duty: 15%; Customs_HS_Code: 85332119; Distributor_name: DIGIKEY; Distributor_part_number: P6.8KJCT-ND; Footprint Path: Y:\MIS_DATABASE\Library\ALTIUM_TOOL\PCB_FOOTPRINTS\Altium_Footprint_Lib.PcbLib; Height: 0.40MM; Library Path: Y:\MIS_DATABASE\Library\ALTIUM_TOOL\SCHEMATICS_PARTS\MS_DISCRETE_Library.schlib; Manufacturer: PANASONIC-ECG; Mfr_name: PANASONIC-ECG; Mfr_part_number: ERJ-2GEJ682X; Mistral Part No: 110009100002-R; Package: 0402; Part_type: RESISTORS\FIXED; Project: BUG_BASE_PIM; RoHS: RoHS; Temperature: -55°C+155°C; Tolerance: 5%; Voltage: NA; Wattage: 1/10W; Weight: 0.8mg; Datasheet: Y:\MIS_DATABASE\DATASHEETS\RESISTORS\PAN-ERJSER_NOV17.PDF
R26 = RESISTOR: RES 49.9K 1/16W 1% 0402; Chkd/date: MAZHAR/220709; Crtd /date: GEETHA/090606; Custom_Duty: 15%; Customs_HS_Code: 85332119; Distributor_name: DIGIKEY; Distributor_part_number: 311-49.9KLRCT-ND; Footprint Path: Y:\MIS_DATABASE\Library\ALTIUM_TOOL\PCB_FOOTPRINTS\Altium_Footprint_Lib.PcbLib; Height: 0.40MM; Library Path: Y:\MIS_DATABASE\Library\ALTIUM_TOOL\SCHEMATICS_PARTS\MS_DISCRETE_Library.schlib; Manufacturer: YAGEO AMERICA; Mfr_name: YAGEO AMERICA; Mfr_part_number: RC0402FR-0749K9L; Mistral Part No: 110009030902-R; Package: 0402; Part_type: RESISTORS\FIXED; Project: PNAV; RoHS: RoHS; Temperature: -55°C+155°C; Tolerance: 1%; Voltage: NA; Wattage: 1/16W; Weight: 0.65mg; Datasheet: Y:\MIS_DATABASE\DATASHEETS\RESISTORS\RCXXXXL-SER_MAR18.PDF
R28 R747 R748 = RESISTOR: RES 100K 1/10W 5% 0402; Chkd/date: VASANTHA/291216; Crtd /date: GEETHA/190406; Custom_Duty: 15%; Customs_HS_Code: 85332119; Distributor_name: DIGIKEY; Distributor_part_number: P100KJCT-ND; Footprint Path: Y:\MIS_DATABASE\Library\ALTIUM_TOOL\PCB_FOOTPRINTS\Altium_Footprint_Lib.PcbLib; Height: 0.40MM; Library Path: Y:\MIS_DATABASE\Library\ALTIUM_TOOL\SCHEMATICS_PARTS\MS_DISCRETE_Library.schlib; Manufacturer: PANASONIC-ECG; Mfr_name: PANASONIC-ECG; Mfr_part_number: ERJ-2GEJ104X; Mistral Part No: 110009030177-R; Package: 0402; Part_type: RESISTORS\FIXED; Project: RED EYE; RoHS: RoHS; Temperature: -55°C+155°C; Tolerance: 5%; Voltage: NA; Wattage: 1/10W; Weight: 0.8mg; Datasheet: Y:\MIS_DATABASE\DATASHEETS\RESISTORS\PAN-ERJSER_NOV17.PDF
R730 = RESISTOR: RES 1M 1/8W 1% 0805; Chkd/date: VASANTHA/150514; Crtd /date: BALACHANDAR/150514; Custom_Duty: 15%; Customs_HS_Code: 85332119; Distributor_name: DIGIKEY; Distributor_part_number: P1.00MCCT-ND; Footprint Path: Y:\MIS_DATABASE\Library\ALTIUM_TOOL\PCB_FOOTPRINTS\Altium_Footprint_Lib.PcbLib; Height: 0.70MM; Library Path: Y:\MIS_DATABASE\Library\ALTIUM_TOOL\SCHEMATICS_PARTS\MS_DISCRETE_Library.schlib; Manufacturer: PANASONIC-ECG; Mfr_name: PANASONIC-ECG; Mfr_part_number: ERJ-6ENF1004V; Mistral Part No: 110014100002-R; Package: 0805; Part_type: RESISTORS\FIXED; Project: HUMANWARE_PHOENIX; RoHS: RoHS; Temperature: -55°C+155°C; Tolerance: 1%; Voltage: NA; Wattage: 1/8W; Weight: 4mg; Datasheet: Y:\MIS_DATABASE\DATASHEETS\RESISTORS\PAN-ERJSER_NOV17.PDF
R731 = RESISTOR: RES 499K 1/16W 1% 0402; Chkd/date: SUHAS/290910; Crtd /date: MAZHAR/240909; Custom_Duty: 15%; Customs_HS_Code: 85332119; Distributor_name: DIGIKEY; Distributor_part_number: 311-499KLRCT-ND; Footprint Path: Y:\MIS_DATABASE\Library\ALTIUM_TOOL\PCB_FOOTPRINTS\Altium_Footprint_Lib.PcbLib; Height: 0.40MM; Library Path: Y:\MIS_DATABASE\Library\ALTIUM_TOOL\SCHEMATICS_PARTS\MS_DISCRETE_Library.schlib; Manufacturer: YAGEO AMERICA; Mfr_name: YAGEO AMERICA; Mfr_part_number: RC0402FR-07499KL; Mistral Part No: 110009090015-R; Package: 0402; Part_type: RESISTORS\FIXED; Project: GOLDEN-I; RoHS: RoHS; Temperature: -55°C+155°C; Tolerance: 1%; Voltage: NA; Wattage: 1/16W; Weight: 0.65mg; Datasheet: Y:\MIS_DATABASE\DATASHEETS\RESISTORS\RCXXXXL-SER_MAR18.PDF
R732 = RESISTOR: RES 910K 1/16W 5% 0402; Chkd/date: BAVISH/111011; Crtd /date: CHAITHANYA/111011; Custom_Duty: 15%; Customs_HS_Code: 85332119; Distributor_name: DIGIKEY; Distributor_part_number: RMCF0402JT910KCT-ND; Footprint Path: Y:\MIS_DATABASE\Library\ALTIUM_TOOL\PCB_FOOTPRINTS\Altium_Footprint_Lib.PcbLib; Height: 0.40MM; Library Path: Y:\MIS_DATABASE\Library\ALTIUM_TOOL\SCHEMATICS_PARTS\MS_DISCRETE_Library.schlib; Manufacturer: STACKPOLE ELECTRONICS; Mfr_name: STACKPOLE ELECTRONICS; Mfr_part_number: RMCF0402JT910K; Mistral Part No: 110011100017-R; Package: 0402; Part_type: RESISTORS\FIXED; Project: VIDEO-GADGET; RoHS: RoHS; Temperature: -55°C+155°C; Tolerance: 5%; Voltage: NA; Wattage: 1/16W; Weight: 0.57mg; Datasheet: Y:\MIS_DATABASE\DATASHEETS\RESISTORS\RMCF-SER_JUL18.PDF
R739 R744 R753 = RESISTOR: RES 200K 1/10W 5% 0402; Chkd/date: MANOJ/230414; Crtd /date: USMAN/151013; Custom_Duty: 15%; Customs_HS_Code: 85332119; Distributor_name: DIGIKEY; Distributor_part_number: P200KJCT-ND; Footprint Path: Y:\MIS_DATABASE\Library\ALTIUM_TOOL\PCB_FOOTPRINTS\Altium_Footprint_Lib.PcbLib; Height: 0.40MM; Library Path: Y:\MIS_DATABASE\Library\ALTIUM_TOOL\SCHEMATICS_PARTS\MS_DISCRETE_Library.schlib; Manufacturer: PANASONIC-ECG; Mfr_name: PANASONIC-ECG; Mfr_part_number: ERJ-2GEJ204X; Mistral Part No: 110013100006-R; Package: 0402; Part_type: RESISTORS\FIXED; Project: C-BAND_SYNTH; RoHS: RoHS; Temperature: -55°C+155°C; Tolerance: 5%; Voltage: NA; Wattage: 1/10W; Weight: 0.8mg; Datasheet: Y:\MIS_DATABASE\DATASHEETS\RESISTORS\PAN-ERJSER_NOV17.PDF
R743 = RESISTOR: RES 200K 1/10W 5% 0402; Assembly_Instruction: DNI; Chkd/date: MANOJ/230414; Crtd /date: USMAN/151013; Custom_Duty: 15%; Customs_HS_Code: 85332119; Distributor_name: DIGIKEY; Distributor_part_number: P200KJCT-ND; Footprint Path: Y:\MIS_DATABASE\Library\ALTIUM_TOOL\PCB_FOOTPRINTS\Altium_Footprint_Lib.PcbLib; Height: 0.40MM; Library Path: Y:\MIS_DATABASE\Library\ALTIUM_TOOL\SCHEMATICS_PARTS\MS_DISCRETE_Library.schlib; Manufacturer: PANASONIC-ECG; Mfr_name: PANASONIC-ECG; Mfr_part_number: ERJ-2GEJ204X; Mistral Part No: 110013100006-R; Package: 0402; Part_type: RESISTORS\FIXED; Project: C-BAND_SYNTH; RoHS: RoHS; Temperature: -55°C+155°C; Tolerance: 5%; Voltage: NA; Wattage: 1/10W; Weight: 0.8mg; Datasheet: Y:\MIS_DATABASE\DATASHEETS\RESISTORS\PAN-ERJSER_NOV17.PDF
R745 = RESISTOR: RES 5.1K 1/10W 1% 0402; Chkd/date: JEBRAN/260315; Crtd /date: CHAITHANYA/270912; Custom_Duty: 15%; Customs_HS_Code: 85332119; Distributor_name: DIGIKEY; Distributor_part_number: P5.10KLCT-ND; Footprint Path: Y:\MIS_DATABASE\Library\ALTIUM_TOOL\PCB_FOOTPRINTS\Altium_Footprint_Lib.PcbLib; Height: 0.40MM; Library Path: Y:\MIS_DATABASE\Library\ALTIUM_TOOL\SCHEMATICS_PARTS\MS_DISCRETE_Library.schlib; Manufacturer: PANASONIC-ECG; Mfr_name: PANASONIC-ECG; Mfr_part_number: ERJ-2RKF5101X; Mistral Part No: 110012090014-R; Package: 0402; Part_type: RESISTORS\FIXED; Project: ITS-CONTROLER_CARD; RoHS: RoHS; Temperature: -55°C+155°C; Tolerance: 1%; Voltage: NA; Wattage: 1/10W; Weight: 0.8mg; Datasheet: Y:\MIS_DATABASE\DATASHEETS\RESISTORS\PAN-ERJSER_NOV17.PDF
R752 = RESISTOR: RES 0E 1/10W JUMPER 0402; Assembly_Instruction: DNI; Chkd/date: VASANTHA/061216; Crtd /date: NAVEED/201014; Custom_Duty: 15%; Customs_HS_Code: 85332119; Distributor_name: DIGIKEY; Distributor_part_number: P0.0JCT-ND; Footprint Path: Y:\MIS_DATABASE\Library\ALTIUM_TOOL\PCB_FOOTPRINTS\Altium_Footprint_Lib.PcbLib; Height: 0.40MM; IBISSP_MODLES: VALUE REPEATING 2 TIME; Library Path: Y:\MIS_DATABASE\Library\ALTIUM_TOOL\SCHEMATICS_PARTS\MS_DISCRETE_Library.schlib; Manufacturer: PANASONIC-ECG; Mfr_name: PANASONIC-ECG; Mfr_part_number: ERJ-2GE0R00X; Mistral Part No: 110018030052-R; Package: 0402; Part_type: RESISTORS\FIXED; Project: AEGIS POM; RoHS: RoHS; Temperature: -55°C+155°C; Tolerance: NA; Voltage: NA; Wattage: 1/10W; Weight: 0.8mg; Datasheet: Y:\MIS_DATABASE\DATASHEETS\RESISTORS\PAN-ERJSER_NOV17.PDF
TP1 = TESTPOINT: TESTPOINT 1.0MM DRILL PTH; Chkd/date: MAZHAR/271211; Crtd /date: SHREESHAIL/041005; Distributor_name: NA; Distributor_part_number: NA; Height: NA; Manufacturer: LOCAL; Mfr_name: LOCAL; Mistral Part No: 130009030938; Package: THRU-HOLE; Project: HSE; Datasheet: NA
TP4 TP252-TP254 = TESTPOINT: TESTPOINT CIR 30 SMD; Chkd/date: SHREESHAIL/171006; Crtd /date: MAZHAR/171006; Custom_Duty: NA; Customs_HS_Code: NA; Distributor_name: NA; Distributor_part_number: NA; Footprint Path: Y:\MIS_DATABASE\Library\ALTIUM_TOOL\PCB_FOOTPRINTS\Altium_Footprint_Lib.PcbLib; Height: NA; Library Path: Y:\MIS_DATABASE\Library\ALTIUM_TOOL\SCHEMATICS_PARTS\MS_DISCRETE_Library.schlib; MECHANICAL 3D STEP FILE: NA; Manufacturer: LOCAL; Mfr_name: LOCAL; Mistral Part No: 130009030930; Package: SMD; Project: BT MODULE_CSRBC04; RoHS: NA; Temperature: NA; Tolerance: NA; Voltage: NA; Wattage: NA; Weight: NA; Datasheet: NA
U1 = MOSFET_CSD85312Q3E: IC MOSFET DUAL N-CHANNEL NEXFET 20V VSON8; Chkd/date: MANIRAJA/270718; Crtd /date: ALVY/240718; Custom_Duty: 15%; Customs_HS_Code: 85423100; Distributor_name: DIGIKEY; Distributor_part_number: 296-37187-1-ND; Footprint Path: Y:\MIS_DATABASE\Library\ALTIUM_TOOL\PCB_FOOTPRINTS\Altium_Footprint_Lib.PcbLib; Height: 1.00MM; Library Path: Y:\MIS_DATABASE\Library\ALTIUM_TOOL\SCHEMATICS_PARTS\MS_MOSFET_Library.schlib; Manufacturer: TEXAS INSTRUMENTS; Mfr_name: TEXAS INSTRUMENTS; Mistral Part No: 142018070009-R; Package: VSON8; Part_type: ICS\POWER\MOSFET; Project: TI_J7SVB_USB_ADD-ON-CARD; RoHS: RoHS; Temperature: -55°C+150°C; Tolerance: NA; Voltage: NA; Wattage: NA; Weight: 32mg; Datasheet: Y:\MIS_DATABASE\DATASHEETS\ICS\POWER\CSD85312Q3E.PDF
U4 U7 U162 = MOSFET_2N7002_SOT23_v2: IC MOSFET N-CHANNEL 50V 200mA SOT23-123; Chkd/date: MANIRAJA/190618; Crtd /date: USMAN/240709; Custom_Duty: 15%; Customs_HS_Code: 85423100; Distributor_name: DIGIKEY; Distributor_part_number: BSS138-FDICT-ND; Footprint Path: Y:\MIS_DATABASE\Library\ALTIUM_TOOL\PCB_FOOTPRINTS\Altium_Footprint_Lib.PcbLib; Height: 1.10MM; Library Path: Y:\MIS_DATABASE\Library\ALTIUM_TOOL\SCHEMATICS_PARTS\MS_MOSFET_Library.schlib; Library Ref: MOSFET_2N7002_SOT23; Manufacturer: DIODES INC; Mfr_name: DIODES INC; Mistral Part No: 142009070019-R; Package: SOT23-123; Part_type: ICS\POWER\MOSFET; Project: KHAN_MAIN; RoHS: RoHS; Temperature: -55°C+150°C; Tolerance: NA; Voltage: 50V; Wattage: 300mW; Weight: 8mg; Datasheet: Y:\MIS_DATABASE\DATASHEETS\DISCRETES\TRANSISTORS_FETS\BSS138.PDF
U5 U164 = TPD2E007DCK_SC70-3: IC AUTOMOTIVE 2-CH HIGH SPEED ESD PROTECTION DEVICE SC70-3; Chkd/date: MANIRAJA/180918; Crtd /date: ALVY/180918; Custom_Duty: 15%; Customs_HS_Code: 85423100; Distributor_name: DIGIKEY; Distributor_part_number: 296-44302-1-ND; Footprint Path: Y:\MIS_DATABASE\Library\ALTIUM_TOOL\PCB_FOOTPRINTS\Altium_Footprint_Lib.PcbLib; Height: 1.10MM; Library Path: Y:\MIS_DATABASE\Library\ALTIUM_TOOL\SCHEMATICS_PARTS\MS_MISCINTERFACE_Library.schlib; Manufacturer: TEXAS INSTRUMENTS; Mfr_name: TEXAS INSTRUMENTS; Mfr_part_number: TPD2E2U06QDCKRQ1; Mistral Part No: 141018090015-R; Package: SC70-3; Part_type: ICS\INTERFACE; Project: TI_J7ES_EVM_CP; RoHS: RoHS; Temperature: -40°C+125°C; Tolerance: NA; Voltage: NA; Wattage: NA; Weight: NA; Datasheet: Y:\MIS_DATABASE\DATASHEETS\ICS\INTERFACE\TPD2E2U06-Q1.PDF
U8 = TPS25830WQRHBQ1_VQFN32_TI: IC USB TYPE-C 3.5A OUTPUT 36V INPUT SYNC STEP DOWN REGULATOR VQFN32; Chkd/date: MANIRAJA/040119; Crtd /date: ALVY/040119; Custom_Duty: 15%; Customs_HS_Code: 85423100; Distributor_name: NA; Distributor_part_number: NA; Footprint Path: Y:\MIS_DATABASE\Library\ALTIUM_TOOL\PCB_FOOTPRINTS\Altium_Footprint_Lib.PcbLib; Height: 1.00MM; Library Path: Y:\MIS_DATABASE\Library\ALTIUM_TOOL\SCHEMATICS_PARTS\MS_MISCPOWER_Library.schlib; Library Ref: TPS25830WQRHBQ1_VQFN32; Manufacturer: TEXAS INSTRUMENTS; Mfr_name: TEXAS INSTRUMENTS; Mistral Part No: 142019010005-R; Package: VQFN32; Part_type: ICS\POWER\VOLTAGE REGULATOR; Project: TI_J7ES_EVM_SOM; RoHS: RoHS; Temperature: -40°C+125°C; Tolerance: NA; Voltage: NA; Wattage: NA; Weight: NA; Datasheet: Y:\MIS_DATABASE\DATASHEETS\ICS\POWER\TPS2583X-Q1.PDF
U158 = TUSB321RWB_X2QFN12_TI: IC USB TYPE-C CH LOGIC AND PORT CONTROL WITH VCONN X2QFN12; Chkd/date: MANIRAJA/140618; Crtd /date: ALVY/130618; Custom_Duty: 15%; Customs_HS_Code: 85423100; Distributor_name: DIGIKEY; Distributor_part_number: 296-42400-1-ND; Footprint Path: Y:\MIS_DATABASE\Library\ALTIUM_TOOL\PCB_FOOTPRINTS\Altium_Footprint_Lib.PcbLib; Height: 0.40MM; Library Path: Y:\MIS_DATABASE\Library\ALTIUM_TOOL\SCHEMATICS_PARTS\MS_MISCINTERFACE_Library.schlib; Library Ref: TUSB321RWB_X2QFN12; Manufacturer: TEXAS INSTRUMENTS; Mfr_name: TEXAS INSTRUMENTS; Mistral Part No: 141018060007-R; Package: X2QFN12; Part_type: ICS\INTERFACE; Project: TI_J7SVB_USB_ADD-ON-CARD; RoHS: RoHS; Temperature: 0°C+70°C; Tolerance: NA; Voltage: NA; Wattage: NA; Weight: 5mg; Datasheet: Y:\MIS_DATABASE\DATASHEETS\ICS\INTERFACE\TUSB321.PDF
U161 = SN74LVC1G08DBVRE4_SOT23-5: IC SINGLE 2-INPUT POSITIVE AND GATE SOT23-5; Automotive Alternate_mfr_name: TEXAS INSTRUMENTS; Automotive Alternate_mfr_part_number: SN74LVC1G08QDBVRQ1; Chkd/date: SUHAS/221010; Crtd /date: USMAN/151008; Custom_Duty: 15%; Customs_HS_Code: 85423100; Distributor_name: DIGIKEY; Distributor_part_number: SN74LVC1G08DBVRE4-ND; Height: 1.45MM; Manufacturer: TEXAS INSTRUMENTS; Mfr_name: TEXAS INSTRUMENTS; Mistral Part No: 141009060026-R; Part_type: ICS\DIGITAL\GATES; Project: KHAN_MAIN; RoHS: Sb/ Br FREE; Temperature: -40°C+85°C; Datasheet: Y:\MIS_DATABASE\DATASHEETS\ICS\DIGITAL\GATES\SN74LVC1G08.PDF
U165 = SN74CBTLV1G125DBVR_SOT23-5: IC LOW VOLTAGE SINGLE FET BUS SW SOT23-5; Automotive Alternate_mfr_name: TEXAS INSTRUMENTS; Automotive Alternate_mfr_part_number: 74CBTLV1G125DBVRQ1; Chkd/date: BAVISH/010311; Crtd /date: MAZHAR/180907; Custom_Duty: 15%; Customs_HS_Code: 85423100; Distributor_name: DIGIKEY; Distributor_part_number: 296-9109-1-ND; Height: 1.45MM; Manufacturer: TEXAS INSTRUMENTS; Mfr_name: TEXAS INSTRUMENTS; Mistral Part No: 142009030140-R; Part_type: ICS\POWER; Project: HSE SERVO; RoHS: RoHS; Temperature: -40°C+85°C; Tolerance: NA; Voltage: NA; Wattage: NA; Weight: NA; Datasheet: Y:\MIS_DATABASE\DATASHEETS\ICS\POWER\SN74CBTLV1G125.PDF
U166 = SI2301CDS_SOT23-3: MOSFET P-CHANNEL 20V 3.1A SOT23-3; Chkd/date: SUHAS/141010; Crtd /date: MUDDU/170310; Custom_Duty: 15%; Customs_HS_Code: 85412900; Distributor_name: DIGIKEY; Distributor_part_number: SI2301CDS-T1-GE3CT-ND; Height: 1.10MM; Manufacturer: VISHAY; Mfr_name: VISHAY; Mistral Part No: 130010030027-P; Package: SOT23-3; Part_type: TRANSISTOR\MOSFET; Project: THERADOME; RoHS: Pb-Free; Temperature: -55°C+150°C; Weight: NA; Datasheet: Y:\MIS_DATABASE\DATASHEETS\DISCRETES\TRANSISTORS_FETS\SI2301CDS-T1-GE3.PDF

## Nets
DGND: C1.2 C2.1 C3.2 C4.2 C5.2 C6.1 C8.2 C9.2 C10.2 C20.1 C26.2 C27.1 C28.2 C323.2 C328.2 C330.2 C331.2 C335.2 C336.2 C338.2 C340.2 C341.2 C343.2 C352.2 C353.2 C354.2 C359.2 C360.2 C361.2 C546.2 C548.1 C559.1 C571.2 C574.2 D1.2(GND) D2.2(GND) D3.2(GND) D4.2(GND) D5.2(GND) D6.2(GND) D7.2(GND) D8.2(GND) J4.A1(GND) J4.A12(GND) J4.B1(GND) J4.B12(GND) R18.2 R21.1 R24.2 R26.2 R28.2 R486.1 R524.1 R531.1 R545.1 R730.1 R743.2 U4.2(SOURCE) U5.3(GND) U8.16(AGND) U8.25(PGND) U8.26(PGND) U8.27(PGND) U8.33(EP) U8.A1 U8.A2 U8.A3 U8.A4 U87.6(GND) U87.11(RS_1/2) U87.17(TPAD) U89.6(GND) U89.11(RS_1/2) U89.17(TPAD) U158.10(GND) U161.3(GND) U162.2(SOURCE) U164.3(GND) U165.2(A) U165.3(GND) ; also on sheet 11 12 13 14 15 16 17 18 20 21 22 23 24 25 26 27 28 29 30 31 32 33 34 35 36 37 38 39 40 41 42 43 44 45 46 47 48 49 50 51 52 55 56 57 58 59 60 61 62 63 64 65 66 67 68 69 70 71 72 73 76 77 78 79 81 82 83 84
VBUS_USBC_CONN: C1.1 J4.A4(VBUS1) J4.A9(VBUS2) J4.B4(VBUS3) J4.B9(VBUS4) R732.2 TP1.1(TP) U1.8(DRAIN2) U8.15(BUS) ; also on sheet 24
VCC_12V0: C26.1 C27.2 C28.1 U8.1(IN1) U8.2(IN2) U8.3(IN3) ; also on sheet 30 31 46 50 59 60 64 66 83
VCC_USBC_PD_5V: C6.2 C8.1 D40.2(ANODE) R746.1 R747.2 R748.2 TP4.1(TP) U8.21(VCC)
VCCA_3V3: C331.1 C338.1 C353.1 C354.1 R504.2 R538.2 R547.2 U87.8(VDD) U89.8(VDD) ; also on sheet 23 69 70 71 72 75 81
VDD1_DDR_1V8: C343.1 U87.4(VMON5) ; also on sheet 14 15 75
VDD_CORE_0V8: C341.1 U87.10(VMON2) ; also on sheet 26 27 28 71 74
VDD_CPU_AVS: C335.1 U87.12(VMON1) ; also on sheet 22 27 28 70 74
VDD_GPIORET_IO_3V3: C359.1 U89.2(VMON6) ; also on sheet 26 69 74
VDD_GPIORET_WK_0V8: C323.1 U89.10(VMON2) ; also on sheet 26 74
VDD_IO_3V3: C336.1 U87.2(VMON6) ; also on sheet 26 72 74
VDD_MCU_0V85: C328.1 U89.12(VMON1) ; also on sheet 26 27 28 69 72 74
VDD_MCUIO_1V8: C352.1 C360.1 C361.1 U89.1(VMON3) U89.3(VMON4) U89.4(VMON5) ; also on sheet 26 69 74
VDD_MCUIO_3V3: R528.2 ; also on sheet 26 72 74
VDD_TUSB321: C546.1 C548.2 D40.1(CATHODE) R8.2 R731.1 R739.1 R744.1 R753.1 U158.12(VDD) U166.2(S)
EN_3V3_VIO: R546.2 ; also on sheet 65 69 72
H_WKUP_I2C0_SCL: U87.16(SCL) U89.16(SCL) ; also on sheet 23 69 70 71
H_WKUP_I2C0_SDA: U87.15(SDA) U89.15(SDA) ; also on sheet 23 69 70 71
MAIN_PWRGRP_IRQn: R487.1 ; also on sheet 69 70 71 72
MAIN_SVS_SLEEPn: R546.1 U87.7(nSLEEP)
MCU_PWRGRP_IRQn: R504.1 R512.1 ; also on sheet 69 72
MCU_SVS_SLEEPn: R528.1 R531.2 U89.7(nSLEEP)
SVS_ENABLE: R545.2 U87.5(ACT) U89.5(ACT) ; also on sheet 23
SVS_SYNCn: R538.1 U87.9(nSYNC) U89.9(nSYNC)
USB0_DATA_N: L7.4(OUT2) ; also on sheet 24
USB0_DATA_P: L7.1(IN1) ; also on sheet 24
USB0_DRVVBUS: U161.1(A) ; also on sheet 24
USB0_ID: R752.2 U165.4(B) ; also on sheet 24
USBC_CC1: J4.A5(CC1) U158.1(CC1) U164.2(IO2)
USBC_CC2: J4.B5(CC2) U158.2(CC2) U164.1(IO1)
USBC_CTRL1_SW: R763.2 R764.1 U162.3(DRAIN)
USBC_CURRENT_MODE: R731.2 U158.3(CURRENT_MODE)
USBC_DATA_CONN_N: J4.A7(D-_1) J4.B7(D-_2) L7.3(OUT1) U5.1(IO1)
USBC_DATA_CONN_P: J4.A6(D+_1) J4.B6(D+_2) L7.2(IN2) U5.2(IO2)
USBC_DIR_SOC: R734.1 U158.11(DIR) ; also on sheet 16
USBC_EARTH: C2.2 J4.SH1 J4.SH2 J4.SH3 J4.SH4 R730.2
USBC_ID: R745.1 U158.9(ID) U165.1(~{OE})
USBC_MODE_SEL0: U7.1(GATE) ; also on sheet 35 38
USBC_MODE_SEL1: U4.1(GATE) U162.1(GATE) ; also on sheet 35 38
USBC_OUT1: R743.1 R753.2 TP253.1(TP) U158.7(OUT1)
USBC_OUT2: R744.2 TP254.1(TP) U158.8(OUT2)
USBC_PD_BOOT: C568.2 U8.32(BOOT)
USBC_PD_CC1: R745.2 U8.20(CC1)
USBC_PD_CSN/OUT: C3.1 C7.1 C20.2 R6.2 U1.1(DRAIN1) U8.13(CSN/OUT)
USBC_PD_CSP: R11.1 U8.14(CSP)
USBC_PD_CTRL1: U8.5(CTRL1) U161.4(Y)
USBC_PD_CTRL2: R28.1 U8.6(CTRL2)
USBC_PD_FAULT#: R748.1 U8.24(~{FAULT})
USBC_PD_ILIMIT: R18.1 U8.12(ILIMIT)
USBC_PD_IMON: R24.1 U8.11(IMON)
USBC_PD_LD_DET#: R746.2 R752.1 U8.23(~{LD_DET}) U166.1(G)
USBC_PD_LS_GD: U1.5(GATE) U8.10(LS_GD)
USBC_PD_POL#: R747.1 U8.22(~{POL})
USBC_PD_RT/SYNC: R26.1 U8.9(RT/SYNC)
USBC_PD_SW: C568.1 L4.1 U8.28(SW1) U8.29(SW2) U8.30(SW3) U8.31(SW4)
USBC_PORT: R8.1 R10.1 R16.1 U158.4(PORT)
USBC_PORT_SW1: R10.2 U4.3(DRAIN)
USBC_PORT_SW2: R16.2 U7.3(DRAIN)
USBC_PWR_EN: R783.2 U8.4(EN/UVLO) ; also on sheet 38
USBC_SS_RX1_CONN_N: D2.1(I/O) J4.B10(RX1-) L3.2(IN2)
USBC_SS_RX1_CONN_P: D4.1(I/O) J4.B11(RX1+) L3.3(OUT1)
USBC_SS_RX1_N: L3.1(IN1) ; also on sheet 12
USBC_SS_RX1_P: L3.4(OUT2) ; also on sheet 12
USBC_SS_RX2_CONN_N: D6.1(I/O) J4.A10(RX2-) L5.2(IN2)
USBC_SS_RX2_CONN_P: D5.1(I/O) J4.A11(RX2+) L5.3(OUT1)
USBC_SS_RX2_N: L5.1(IN1) ; also on sheet 12
USBC_SS_RX2_P: L5.4(OUT2) ; also on sheet 12
USBC_SS_TX1_CONN_N: D7.1(I/O) J4.A3(TX1-) L6.3(OUT1)
USBC_SS_TX1_CONN_P: D8.1(I/O) J4.A2(TX1+) L6.2(IN2)
USBC_SS_TX1_N: L6.4(OUT2) ; also on sheet 12
USBC_SS_TX1_P: L6.1(IN1) ; also on sheet 12
USBC_SS_TX2_CONN_N: D1.1(I/O) J4.B3(TX2-) L2.3(OUT1)
USBC_SS_TX2_CONN_P: D3.1(I/O) J4.B2(TX2+) L2.2(IN2)
USBC_SS_TX2_N: L2.4(OUT2) ; also on sheet 12
USBC_SS_TX2_P: L2.1(IN1) ; also on sheet 12
USBC_VBUS_DET: R732.1 U158.5(VBUS_DET)
USBC_VCON_FAULT#: R739.2 TP252.1(TP) U158.6(~{VCONN_FAULT})
VCSP_USBC_PD: C4.1 C5.1 C7.2 C9.1 C10.1 C559.2 L4.2 R6.1 R11.2 U166.3(D)
VDA_PHY_1V8: C340.1 U87.3(VMON4) ; also on sheet 25 74
VDA_PLL_1V8: C330.1 U87.1(VMON3) ; also on sheet 25 74
VSYS_IO_3V3: C571.1 C574.1 R764.2 R783.1 U161.5(VCC) U165.5(VCC) ; also on sheet 18 20 22 24 29 30 31 32 33 35 36 37 38 40 41 42 43 45 46 48 50 51 56 57 58 59 60 61 65 66 68 75 81 82
VSYS_MCUIO_1V8: R734.2 ; also on sheet 17 21 37 39 62 65 75
N28043247: R763.1 U161.2(B)
N28389101: R21.2 U7.2(SOURCE)
N34900604: R486.2 U87.14(ADDR)
N34900686: R524.2 U89.14(ADDR)
N37510034: R487.2 R547.1 U87.13(nINQ)
N37510108: R512.2 U89.13(nINQ)

Not connected (* = marked no-connect by the designer): J4 A8(SBU1)* B8(SBU2)*; U1 9(SOURCE)*; U8 7(DP_OUT)* 8(DM_OUT)* 17(DM_IN)* 18(DP_IN)* 19(CC2)*

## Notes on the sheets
sheet 53
- USB 3.1 TYPE C INTERFACE
- Note:VCC_USBC_PD_5V is Output of internal bias supply.
- Note: Control to enable/powerdown circuit.
- ILIMIT (max) = 1.5A
- Note: Control to enable/disable VBUS.
- PCB Note: Place
  Capacitor C close to the
  IC pin
- (for connecting to
  USB0_SOC_VBUS)
- Note:DIP Switch/User Selectable.
- USBC_MODE_SEL[1:0]: '00' = DFP
                      '01' = DRP
                      '1x' = UFP
- Iout (max) = 1.5A
- 90E
- Note: Type C Cable Polarity Detection.
- '0' - Position 1, '1' - Position 2
- 90E
- Silkscreen
  "USB-C"
- 90E
- 90E
- 90E
sheet 54
- Safety Voltage Supervisors
- Power rail voltage > 1.0V can
  connect to VMON3-6 inputs
  using single-ended traces.
  Trace widths = 4-8mil, as short as possible
  & try to avoid routing near HF signals.
- Any power rail voltage < 1.0V should
  connect to VMON1 & VMON2 inputs
  using "Pseudo Diff Pair Trace" routes.
  Trace widths = 4-8mil & Separation  = 8-50mil,
  try to keep traces near each other.
- VMON1 & VMON2 use a common return trace connected to
  RS_12 pin. Route as pseudo diff pair with return trace
  connected to Gnd at point of sense located in between
  VMON1 & VMON2 attachment points.
- R Value sets I2C ADDR
  5.36k      =>  0x30
- R Value sets I2C ADDR
  16.2k      =>  0x31
